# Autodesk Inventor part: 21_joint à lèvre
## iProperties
Shininess: 20.0
Length Units: 11270
Angle Units: 11279
Time Units: 11290
Mass Units: 11283
Length Display Precision: 3
Angle Display Precision: 2
Created: 2000-10
Part Number: 21_joint à lèvre
Material: Par défaut
Document SubType Name: Modélisation
Density: 0.0
Volumn: 0.0
Area: 0.0
PropertySet Name: Model Information
Control State: 0
Master: False
Checked Out: False
Author: Laurent GAUTHERON
